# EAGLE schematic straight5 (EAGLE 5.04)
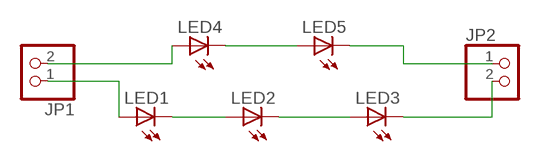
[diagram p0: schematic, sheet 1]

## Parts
JP1  PINHD-1X2  [1X02]
JP2  PINHD-1X2  [1X02]
LED1  LED5MM  [LED5MM]
LED2  LED5MM  [LED5MM]
LED3  LED5MM  [LED5MM]
LED4  LED5MM  [LED5MM]
LED5  LED5MM  [LED5MM]

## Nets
N$1: JP1.1 LED1.A
N$2: LED1.K(C) LED2.A
N$3: LED2.K(C) LED3.A
N$4: JP2.2 LED3.K(C)
N$5: JP1.2 LED4.A
N$6: LED4.K(C) LED5.A
N$7: JP2.1 LED5.K(C)

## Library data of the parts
JP1 JP2 = pinhead:PINHD-1X2: PIN HEADER
LED1-LED5 = led:LED: LED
